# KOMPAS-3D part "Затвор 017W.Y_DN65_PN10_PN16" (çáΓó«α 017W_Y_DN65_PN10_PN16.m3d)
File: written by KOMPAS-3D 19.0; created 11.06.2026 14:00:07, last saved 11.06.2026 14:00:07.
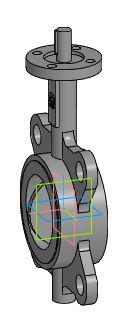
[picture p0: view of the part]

Document properties: Автор: Евгений; Полное имя файла: Z:\3.Личные\kachalov\001_3d для проектировщиков\x.x Тип 017W.Y(S) Затвор дисковый поворотный межфланцевый\_stp_Затвор 017W.Y_DN50-DN350\Затвор 017W_Y_DN65_PN10_PN16.m3d

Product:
- Part/product: Затвор 017W.Y_DN65_PN10_PN16

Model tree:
1. Операция без истории:1  (labels: Затвор 017W.Y_DN65_PN10_PN16)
